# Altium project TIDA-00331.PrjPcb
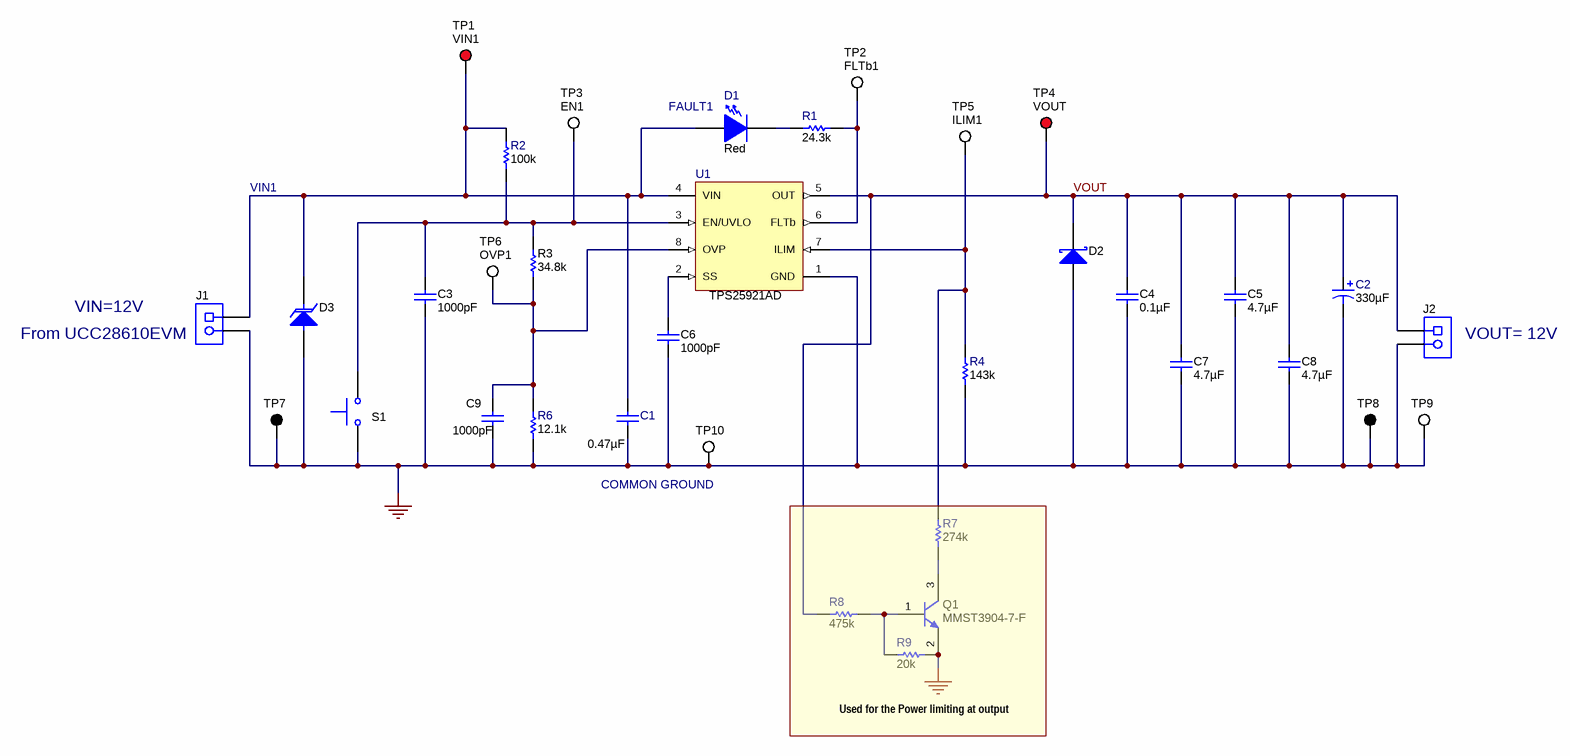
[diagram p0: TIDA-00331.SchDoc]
CopyrightYear: 2014; PCB_Layout: Who did the Layout?; PCB_Rev: E1; PRJ_Customer: Public Release; PRJ_Engineer: Enter name of project lead; PRJ_Number: XX####; PRJ_Title: Change in menu Project|Project Options|Parameters; SCH_Rev: E1; TechSupport: http://www.ti.com/support
1 sheet, 35 parts. Net scope: global (net labels, ports and power ports of the same name join across sheets).
Board file: TIDA-00331.PcbDoc

## Sheet TIDA-00331.SchDoc
size 431 x 279 mm; Date: Not shown in title block; ApprovedBy: Not shown in title block; CheckedBy: Not shown in title block; Author: Not shown in title block; CompanyName: Not shown in title block; DrawnBy: Dinesh Kumar; Engineer: Not shown in title block; Organization: Not shown in title block; Address1: Not shown in title block; Address2: Not shown in title block; Address3: Not shown in title block; Address4: Not shown in title block; DocumentNumber: 1; Revision: Use project parameter SCH_Rev; SheetNumber: 1; SheetTotal: 1; PageSetup: Record=PageOptions|CenterHorizontal=True|CenterVertical=True|PrintScale=1.00|XCorrection=1.00|YCorrection=1.00|PrintKind=0|BorderSize=5000000|LeftOffset=0|BottomOffset=0|Orientation=2|PaperLength=1000|PaperWidth=1000|Scale=100|PaperSource=15|PrintQuality=600|MediaType=1|DitherType=10|PaperKind=Letter|PrintScaleMode=1

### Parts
C1  ValueDisplayed: 0.47µF  [1206]  (hidden comment: 12065C474KAT2A)
C2  ValueDisplayed: 330µF  [CAPSMT_62_HA0]  (hidden comment: EMZA250ADA331MHA0G)
C3  ValueDisplayed: 1000pF  [0805_HV]  (hidden comment: 08055C102KAT2A)
C4  ValueDisplayed: 0.1µF  [0805]  (hidden comment: 08053C104KAT2A)
C5  ValueDisplayed: 4.7µF  [0805]  (hidden comment: C2012X5R1E475K125AB)
C6  ValueDisplayed: 1000pF  [0805_HV]  (hidden comment: 08055C102KAT2A)
C7  ValueDisplayed: 4.7µF  [0805]  (hidden comment: C2012X5R1E475K125AB)
C8  ValueDisplayed: 4.7µF  [0805]  (hidden comment: C2012X5R1E475K125AB)
C9  ValueDisplayed: 1000pF  [0805_HV]  (hidden comment: 08055C102KAT2A)
D1  value Red  [LED_LTST-C190_Red]  (hidden comment: LTST-C190CKT)
D2  B320A-13-F  [SMA]  (value not drawn)
D3  SMBJ18A-13-F  [SMB]  (value not drawn)
J1  282841-2  [TEC_282841-2]  (value not drawn)
J2  282841-2  [TEC_282841-2]  (value not drawn)
Q1  MMST3904-7-F  [SOT-323]
R1  value 24.3k  [0805_HV]  (hidden comment: CRCW080524K3FKEA)
R2  value 100k  [0805_HV]  (hidden comment: CRCW0805100KFKEA)
R3  value 34.8k  [0805_HV]  (hidden comment: CRCW080534K8FKEA)
R4  value 143k  [0805_HV]  (hidden comment: CRCW0805143KFKEA)
R6  value 12.1k  [0805_HV]  (hidden comment: CRCW080512K1FKEA)
R7  value 274k  [0805_HV]  (hidden comment: CRCW0805274KFKEA)
R8  value 475k  [0805_HV]  (hidden comment: CRCW0805475KFKEA)
R9  value 20k  [0805_HV]  (hidden comment: CRCW080520K0JNEA)
S1  RES-1  [SW_SKRKAEE010]  (value not drawn)
TP1  VIN1  [Keystone5010]
TP2  FLTb1  [Keystone5012]
TP3  EN1  [Keystone5012]
TP4  VOUT  [Keystone5010]
TP5  ILIM1  [Keystone5012]
TP6  OVP1  [Keystone5012]
TP7  GND  [Keystone5011]  (value not drawn)
TP8  GND  [Keystone5011]  (value not drawn)
TP9  GND  [Testpoint_Keystone_Compact]  (value not drawn)
TP10  GND  [Testpoint_Keystone_Compact]  (value not drawn)
U1  TPS25921AD  [D0008A_N]

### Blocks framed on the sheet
Used for the Power limiting at output: Q1 R7-R9

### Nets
GND: C1.2 C2.2(-) C3.2 C4.2 C5.2 C6.2 C7.2 C8.2 C9.2 D2.2(A) D3.2(A) J1.2 J2.2 Q1.2(E) R4.1 R6.1 R9.1 S1.1 TP7.1 TP8.1 TP9.1 TP10.1 U1.1(GND)
VOUT: C2.1(+) C4.1 C5.1 C7.1 C8.1 D2.1(K) J2.1 R8.2 TP4.1 U1.5(OUT)
NetC1_1: C1.1 D1.1(A) D3.1(K) J1.1 R2.2 TP1.1 U1.4(VIN)
NetC3_1: C3.1 R2.1 R3.2 S1.2 TP3.1 U1.3(EN/UVLO)
NetC6_1: C6.1 U1.2(SS)
NetC9_1: C9.1 R3.1 R6.2 TP6.1 U1.8(OVP)
NetD1_2: D1.2(K) R1.2
NetQ1_1: Q1.1(B) R8.1 R9.2
NetQ1_3: Q1.3(C) R7.1
NetR1_1: R1.1 TP2.1 U1.6(FLTb)
NetR4_2: R4.2 R7.2 TP5.1 U1.7(ILIM)

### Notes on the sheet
- (near D1) FAULT1
- VIN1
- From UCC28610EVM
- VIN=12V
- (near J2) VOUT= 12V
- COMMON GROUND

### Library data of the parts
C1 = 12065C474KAT2A: CAP, CERM, 0.47uF, 50V, +/-10%, X7R, 1206; Manufacturer: AVX; Polarized: N; CompType: Capacitor; U/M: EA; Cap_F: 0.00000047; Tolerance_%: 10; ESR_Ohm: 0.018; Value1: 0.018 ohm; VDC_V: 50; TaMin_C: -55; TaMax_C: 125
C2 = EMZA250ADA331MHA0G: CAP, AL, 330uF, 25V, +/-20%, 0.16 ohm, SMD; Manufacturer: Nippon Chemi-Con; Polarized: Y; CompType: Capacitor; U/M: EA; Cap_F: 0.00033; Tolerance_%: 20; VDC_V: 25; ESR_Ohm: 0.16; IRMS_A: 0.6; TaMin_C: -55; TaMax_C: 105; Cap_Case: HA0
C3 C6 C9 = 08055C102KAT2A: CAP, CERM, 1000pF, 50V, +/-10%, X7R, 0805; Manufacturer: AVX; Polarized: N; CompType: Capacitor; U/M: EA; Cap_F: 0.000000001; Tolerance_%: 10; ESR_Ohm: 0.29; Value1: 0.29 ohm; VDC_V: 50; TaMin_C: -55; TaMax_C: 125; Cap_Case: 0805
C4 = 08053C104KAT2A: CAP, CERM, 0.1uF, 25V, +/-10%, X7R, 0805; Manufacturer: AVX; Polarized: N; CompType: Capacitor; U/M: EA; Cap_F: 0.0000001; Tolerance_%: 10; ESR_Ohm: 0.28; Value1: 0.28 ohm; VDC_V: 25; TaMin_C: -55; TaMax_C: 125
C5 C7 C8 = C2012X5R1E475K125AB: CAP, CERM, 4.7uF, 25V, +/-10%, X5R, 0805; Manufacturer: TDK; Polarized: N; CompType: Capacitor; U/M: EA; Cap_F: 0.0000047; Tolerance_%: 10; Value1: Unknown; VDC_V: 25; TaMin_C: -55; TaMax_C: 85
D1 = LTST-C190CKT: LED, Red, SMD; Manufacturer: Lite-On; Vf_V: 2; Value2: 2V; Io_A: 0.02; Tjmax_C: 85; Power_TotalModule: 0.0625; Value1: 0.0625W; U/M: EA
D2 = B320A-13-F: Diode, Schottky, 20V, 3A, SMA; Manufacturer: Diodes Inc.; U/M: EA; Vf_V: 0.5; Io_A: 3; Vr_V: 20; Value2: 0.5V; TJmax_C: 125; RJC_CperW: 25
D3 = SMBJ18A-13-F: Diode, TVS, Uni, 18V, 600W, SMB; Manufacturer: Diodes Inc.; U/M: EA; Power_W: 5; Vr_V: 18; Value1: 5W
J1 = 282841-2: Terminal Block, 2x1, 5.08mm, TH; Manufacturer: TE Connectivity; SymbolCreator: a0412235; U/M: EA
J2 = 282841-2: Terminal Block, 2x1, 5.08mm, TH; pin to pad: 1>2 2>1; Manufacturer: TE Connectivity; SymbolCreator: a0412235; U/M: EA
Q1 = MMST3904-7-F, Diodes Inc.: Transistor, NPN, 20V, 0.2A, SOT-323; CompType: BJT; PNP: 0; NPN: 1; Vceo_V: 20; Vcesat1_V: 0.3; Value: 0.3V; IcRated_A: 0.2; HfeMax: 300; TaMin_C: -55; TaMax_C: 150; U/M: EA
R1 = CRCW080524K3FKEA: RES, 24.3k ohm, 1%, 0.125W, 0805; Manufacturer: Vishay-Dale; CompType: Resistor; Res_ohm: 24300; Value_Code: 24k3; Tolerance_%: 1; Power_W: 0.125; VDC_V: 150; TempCo: 100 ppm/C; EIA_Code: E96; U/M: EA
R2 = CRCW0805100KFKEA: RES, 100k ohm, 1%, 0.125W, 0805; Manufacturer: Vishay-Dale; CompType: Resistor; Res_ohm: 100000; Tolerance_%: 1; Power_W: 0.125; VDC_V: 150; TempCo: 100 ppm/C; EIA_Code: E96; U/M: EA
R3 = CRCW080534K8FKEA: RES, 34.8k ohm, 1%, 0.125W, 0805; Manufacturer: Vishay-Dale; CompType: Resistor; Res_ohm: 34800; Value_Code: 34k8; Tolerance_%: 1; Power_W: 0.125; VDC_V: 150; TempCo: 100 ppm/C; EIA_Code: E96; U/M: EA
R4 = CRCW0805143KFKEA: RES, 143k ohm, 1%, 0.125W, 0805; Manufacturer: Vishay-Dale; CompType: Resistor; Res_ohm: 143000; Tolerance_%: 1; Power_W: 0.125; VDC_V: 150; TempCo: 100 ppm/C; EIA_Code: E96; U/M: EA
R6 = CRCW080512K1FKEA: RES, 12.1k ohm, 1%, 0.125W, 0805; Manufacturer: Vishay-Dale; CompType: Resistor; Res_ohm: 12100; Value_Code: 12k1; Tolerance_%: 1; Power_W: 0.125; VDC_V: 150; TempCo: 100 ppm/C; EIA_Code: E96; U/M: EA
R7 = CRCW0805274KFKEA: RES, 274k ohm, 1%, 0.125W, 0805; Manufacturer: Vishay-Dale; CompType: Resistor; Res_ohm: 274000; Tolerance_%: 1; Power_W: 0.125; VDC_V: 150; TempCo: 100 ppm/C; EIA_Code: E96; U/M: EA
R8 = CRCW0805475KFKEA: RES, 475k ohm, 1%, 0.125W, 0805; Manufacturer: Vishay-Dale; CompType: Resistor; Res_ohm: 475000; Tolerance_%: 1; Power_W: 0.125; VDC_V: 150; TempCo: 100 ppm/C; EIA_Code: E96; U/M: EA
R9 = CRCW080520K0JNEA: RES, 20k ohm, 5%, 0.125W, 0805; Manufacturer: Vishay-Dale; CompType: Resistor; Res_ohm: 20000; Value_Code: 20k0; Tolerance_%: 5; Power_W: 0.125; VDC_V: 150; TempCo: 200 ppm/C; EIA_Code: E24; U/M: EA
S1 = SKRKAEE010: Switch, Push Button, SMD; Manufacturer: Alps; Alternate Manufacturer: Any; Alternate PartNumber: Equivalent; SymbolCreator: a0412235; Circuit: SPST-NO; VDC_V: 12; SwitchFunction: Off-Mom; PositionCount: 1; CurrentRating_mA: 50
TP1 TP4 = 5010: Test Point, TH, Multipurpose, Red; Manufacturer: Keystone; Alternate Manufacturer: Any; Alternate PartNumber: Equivalent; CompType: Test Point Loop; U/M: EA
TP2 TP3 TP5 TP6 = 5012: Test Point, TH, Multipurpose, White; Manufacturer: Keystone; Alternate Manufacturer: Any; Alternate PartNumber: Equivalent; CompType: Test Point Loop; U/M: EA
TP7 TP8 = 5011: Test Point, TH, Multipurpose, Black; Manufacturer: Keystone; Alternate Manufacturer: Any; Alternate PartNumber: Equivalent; CompType: Test Point Loop; U/M: EA
TP9 TP10 = 5016: Test Point, SMT, Compact; Manufacturer: Keystone; Alternate Manufacturer: Any; Alternate PartNumber: Equivalent; CompType: Test Point Loop; U/M: EA
U1 = TPS25921AD: 4.5-18V eFuse with Precision Current Limit, D0008A; Alternate Manufacturer: None; Manufacturer: Texas Instruments; SymbolCreator: x0208326; CompType: IC; U/M: EA

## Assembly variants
001: not fitted FID1 FID2 FID3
